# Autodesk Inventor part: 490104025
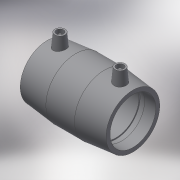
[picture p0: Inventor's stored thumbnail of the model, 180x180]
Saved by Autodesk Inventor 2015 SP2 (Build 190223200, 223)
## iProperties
Created: 2017-06
Part Number: 490104025
Material: Generic
Description: PLASSON COUPLER 25-25
Document SubType Name: Modeling
Designer: KIM
Mass: 43.6263 g
Surface Area: 194.911 cm^2
Volume: 43.6263 cm^3
Density: 1 g/cm^3
Appearance: Default
Author: KIM
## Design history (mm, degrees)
derived "490104.ipt"
feature "Solid1::490104.ipt"
tag "TaggingFeature1"
body "Solid1"
other parameters: "d0" = 82, "d1" = 25, "d2" = 36, "d4" = 27.33333, "d5" = 32.4, "d6" = 23.75, "d7" = 25, "d8" = 168 deg, "d10" = 16, "d11" = 5.33333, "d13" = 82, "d14" = 17.6296, "d17" = 23.75, "d18" = 25, "d19" = 3.52592, "d20" = 168 deg, "d22" = 33.84, "d23" = 36, "d24" = 32.8248, "d25" = 135 deg, "d26" = 32.8, "d27" = 135 deg, "d29" = 37, "d30" = 14, "d31" = 28.7, "d34" = 5 deg, "d35" = 15, "d39" = 5 deg, "d41" = 4, "d42" = 14, "d43" = 0, "d45" = 4, "d46" = 14, "d47" = 0, "d48" = 3, "d49" = 0, "d50" = 3, "d51" = 0, "d52" = 11.6, "d53" = 2.9, "d_" = 25, "L_" = 82, "D_" = 36, "A_" = 37, "d_2" = 12
